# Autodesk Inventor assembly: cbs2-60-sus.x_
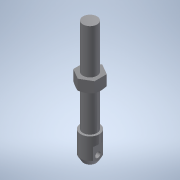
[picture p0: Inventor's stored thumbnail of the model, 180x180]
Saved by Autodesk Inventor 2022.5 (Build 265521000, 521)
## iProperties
Part Number: cbs2-60-sus.x_
Material: 一般
Document SubType Name: Assembly
Designer: ImaoCorp
Sending System: SOLIDWORKS 2017-2017317
MC: AMD64
MC_MODEL: Intel64 Family 6 Model 60 Stepping 3, GenuineIntel
OS: Windows_NT
FRU: Parasolid Version 29.0, build 201,  4-17-2017
FORMAT: text
GUISE: transmit
KEY: cbs2-60-sus
FILE: cbs2-60-sus.x_t
DATE: Thu Apr 04 16:32:45 2019
Author: ImaoCorp
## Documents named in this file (3)
- X:\14_SW2022-Inv2022\00_全2023-1023新製品(TCC)まで\c\cbs2-60-sus\CBS2-60-SUS.iam
- X:\14_SW2022-Inv2022\00_全2023-1023新製品(TCC)まで\c\cbs2-60-sus\cbs2-60-sus_01.ipt
- X:\14_SW2022-Inv2022\00_全2023-1023新製品(TCC)まで\c\cbs2-60-sus\cbs2-60-sus_02.ipt
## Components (2 placed, 2 different names)
1. cbs2-60-sus_01
2. cbs2-60-sus_02
